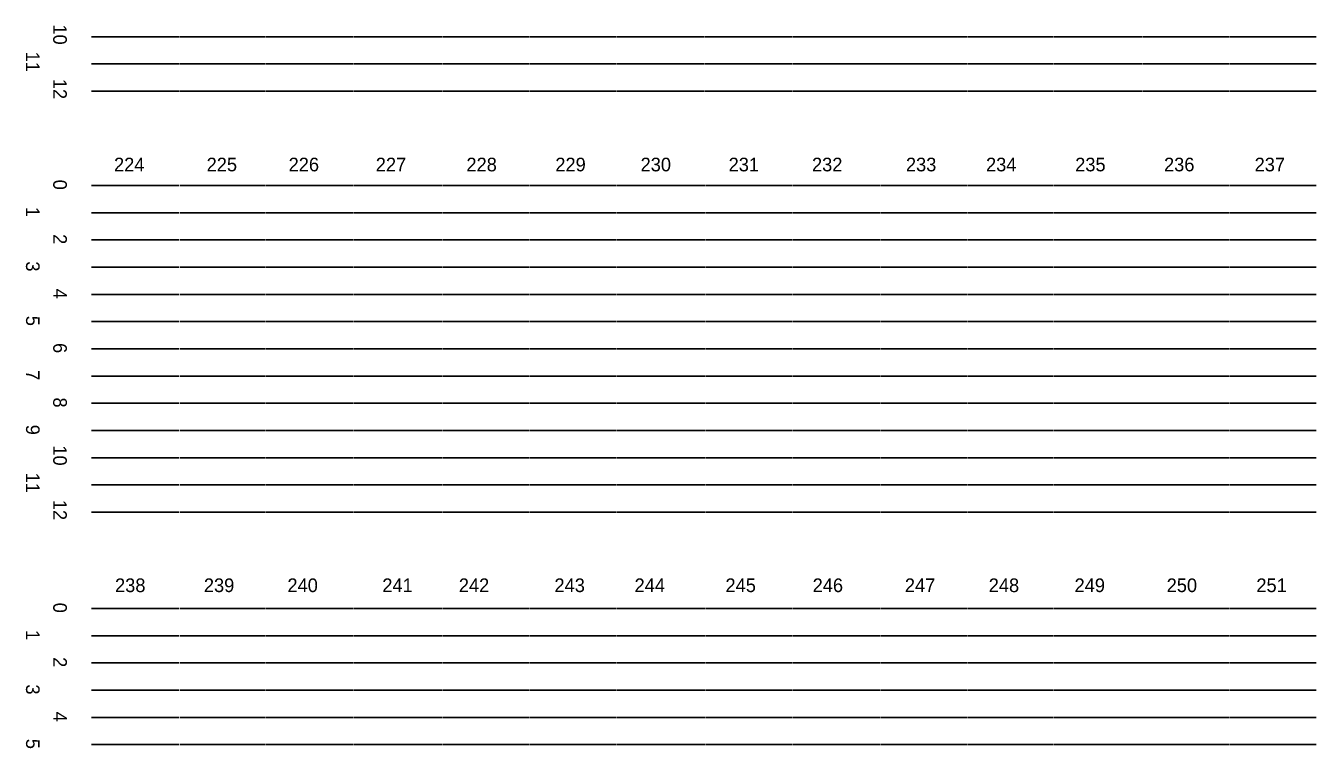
# Model space of a CAD drawing. Extents: x 11193 to 12507, y 10092 to 10555.
# Drawn here: x 11683 to 11888.4, y 10324.2 to 10439.2 of the extents above; entities that cross this region are included whole.
import ezdxf

# ---------------------------------------------------------------- set-up
doc = ezdxf.new("R2010")
doc.units = 0
doc.layers.add('Level 2', color=7, linetype='Continuous')

msp = doc.modelspace()

# ---------------------------------------------------------------- linework, layer by layer
at = {"layer": 'Level 2'}
for p, q in [((11693.42, 10437.46), (11707.34, 10437.46)), ((11707.44, 10437.46), (11721.02, 10437.46)), ((11721.12, 10437.46), (11735.1, 10437.46)), ((11735.2, 10437.46), (11749.18, 10437.46)), ((11749.29, 10437.46), (11763.06, 10437.46)), ((11763.17, 10437.46), (11776.94, 10437.46)), ((11777.05, 10437.46), (11791.02, 10437.46)), ((11791.13, 10437.46), (11804.91, 10437.46)), ((11805.02, 10437.46), (11818.99, 10437.46)), ((11819.09, 10437.46), (11832.87, 10437.46)), ((11832.98, 10437.46), (11846.54, 10437.46)), ((11846.65, 10437.46), (11860.62, 10437.46)), ((11860.73, 10437.46), (11874.51, 10437.46)), ((11874.62, 10437.46), (11888.36, 10437.46)), ((11693.42, 10433.13), (11707.34, 10433.13)), ((11707.44, 10433.13), (11721.02, 10433.13)), ((11721.12, 10433.13), (11735.1, 10433.13)), ((11735.2, 10433.13), (11749.18, 10433.13)), ((11749.29, 10433.13), (11763.06, 10433.13)), ((11763.17, 10433.13), (11776.94, 10433.13)), ((11777.05, 10433.13), (11791.02, 10433.13)), ((11791.13, 10433.13), (11804.91, 10433.13)), ((11805.02, 10433.13), (11818.99, 10433.13)), ((11819.09, 10433.13), (11832.87, 10433.13)), ((11832.98, 10433.13), (11846.54, 10433.13)), ((11846.65, 10433.13), (11860.62, 10433.13)), ((11860.73, 10433.13), (11874.51, 10433.13)), ((11874.62, 10433.13), (11888.36, 10433.13)), ((11693.42, 10428.8), (11707.34, 10428.8)), ((11707.44, 10428.8), (11721.02, 10428.8)), ((11721.12, 10428.8), (11735.1, 10428.8)), ((11735.2, 10428.8), (11749.18, 10428.8)), ((11749.29, 10428.8), (11763.06, 10428.8)), ((11763.17, 10428.8), (11776.94, 10428.8)), ((11777.05, 10428.8), (11791.02, 10428.8)), ((11791.13, 10428.8), (11804.91, 10428.8)), ((11805.02, 10428.8), (11818.99, 10428.8)), ((11819.09, 10428.8), (11832.87, 10428.8)), ((11832.98, 10428.8), (11846.54, 10428.8)), ((11846.65, 10428.8), (11860.62, 10428.8)), ((11860.73, 10428.8), (11874.51, 10428.8)), ((11874.62, 10428.8), (11888.36, 10428.8)), ((11693.42, 10413.78), (11707.35, 10413.78)), ((11707.47, 10413.78), (11721.03, 10413.78)), ((11721.14, 10413.78), (11735.11, 10413.78)), ((11735.23, 10413.78), (11749.19, 10413.78)), ((11749.31, 10413.78), (11763.08, 10413.78)), ((11763.19, 10413.78), (11776.96, 10413.78)), ((11777.06, 10413.78), (11791.04, 10413.78)), ((11791.14, 10413.78), (11804.92, 10413.78)), ((11805.02, 10413.78), (11819.01, 10413.78)), ((11819.11, 10413.78), (11832.88, 10413.78)), ((11832.98, 10413.78), (11846.56, 10413.78)), ((11846.66, 10413.78), (11860.64, 10413.78)), ((11860.74, 10413.78), (11874.52, 10413.78)), ((11874.63, 10413.78), (11888.36, 10413.78)), ((11693.42, 10409.45), (11707.35, 10409.45)), ((11707.47, 10409.45), (11721.03, 10409.45)), ((11721.14, 10409.45), (11735.11, 10409.45)), ((11735.23, 10409.45), (11749.19, 10409.45)), ((11749.31, 10409.45), (11763.08, 10409.45)), ((11763.19, 10409.45), (11776.96, 10409.45)), ((11777.06, 10409.45), (11791.04, 10409.45)), ((11791.14, 10409.45), (11804.92, 10409.45)), ((11805.02, 10409.45), (11819.01, 10409.45)), ((11819.11, 10409.45), (11832.88, 10409.45)), ((11832.98, 10409.45), (11846.56, 10409.45)), ((11846.66, 10409.45), (11860.64, 10409.45)), ((11860.74, 10409.45), (11874.52, 10409.45)), ((11874.63, 10409.45), (11888.36, 10409.45)), ((11693.42, 10405.11), (11707.35, 10405.11)), ((11707.47, 10405.11), (11721.03, 10405.11)), ((11721.14, 10405.11), (11735.11, 10405.11)), ((11735.23, 10405.11), (11749.19, 10405.11)), ((11749.31, 10405.11), (11763.08, 10405.11)), ((11763.19, 10405.11), (11776.96, 10405.11)), ((11777.06, 10405.11), (11791.04, 10405.11)), ((11791.14, 10405.11), (11804.92, 10405.11)), ((11805.02, 10405.11), (11819.01, 10405.11)), ((11819.11, 10405.11), (11832.88, 10405.11)), ((11832.98, 10405.11), (11846.56, 10405.11)), ((11846.66, 10405.11), (11860.64, 10405.11)), ((11860.74, 10405.11), (11874.52, 10405.11)), ((11874.63, 10405.11), (11888.36, 10405.11)), ((11693.42, 10400.78), (11707.35, 10400.78)), ((11707.47, 10400.78), (11721.03, 10400.78)), ((11721.14, 10400.78), (11735.11, 10400.78)), ((11735.23, 10400.78), (11749.19, 10400.78)), ((11749.31, 10400.78), (11763.08, 10400.78)), ((11763.19, 10400.78), (11776.96, 10400.78)), ((11777.06, 10400.78), (11791.04, 10400.78)), ((11791.14, 10400.78), (11804.92, 10400.78)), ((11805.02, 10400.78), (11819.01, 10400.78)), ((11819.11, 10400.78), (11832.88, 10400.78)), ((11832.98, 10400.78), (11846.56, 10400.78)), ((11846.66, 10400.78), (11860.64, 10400.78)), ((11860.74, 10400.78), (11874.52, 10400.78)), ((11874.63, 10400.78), (11888.36, 10400.78)), ((11693.42, 10396.45), (11707.35, 10396.45)), ((11707.47, 10396.45), (11721.03, 10396.45)), ((11721.14, 10396.45), (11735.11, 10396.45)), ((11735.23, 10396.45), (11749.19, 10396.45)), ((11749.31, 10396.45), (11763.08, 10396.45)), ((11763.19, 10396.45), (11776.96, 10396.45)), ((11777.06, 10396.45), (11791.04, 10396.45)), ((11791.14, 10396.45), (11804.92, 10396.45)), ((11805.02, 10396.45), (11819.01, 10396.45)), ((11819.11, 10396.45), (11832.88, 10396.45)), ((11832.98, 10396.45), (11846.56, 10396.45)), ((11846.66, 10396.45), (11860.64, 10396.45)), ((11860.74, 10396.45), (11874.52, 10396.45)), ((11874.63, 10396.45), (11888.36, 10396.45)), ((11693.42, 10392.12), (11707.35, 10392.12)), ((11707.47, 10392.12), (11721.03, 10392.12)), ((11721.14, 10392.12), (11735.11, 10392.12)), ((11735.23, 10392.12), (11749.19, 10392.12)), ((11749.31, 10392.12), (11763.08, 10392.12)), ((11763.19, 10392.12), (11776.96, 10392.12)), ((11777.06, 10392.12), (11791.04, 10392.12)), ((11791.14, 10392.12), (11804.92, 10392.12)), ((11805.02, 10392.12), (11819.01, 10392.12)), ((11819.11, 10392.12), (11832.88, 10392.12)), ((11832.98, 10392.12), (11846.56, 10392.12)), ((11846.66, 10392.12), (11860.64, 10392.12)), ((11860.74, 10392.12), (11874.52, 10392.12)), ((11874.63, 10392.12), (11888.36, 10392.12)), ((11693.42, 10387.79), (11707.35, 10387.79)), ((11707.47, 10387.79), (11721.03, 10387.79)), ((11721.14, 10387.79), (11735.11, 10387.79)), ((11735.23, 10387.79), (11749.19, 10387.79)), ((11749.31, 10387.79), (11763.08, 10387.79)), ((11763.19, 10387.79), (11776.96, 10387.79)), ((11777.06, 10387.79), (11791.04, 10387.79)), ((11791.14, 10387.79), (11804.92, 10387.79)), ((11805.02, 10387.79), (11819.01, 10387.79)), ((11819.11, 10387.79), (11832.88, 10387.79)), ((11832.98, 10387.79), (11846.56, 10387.79)), ((11846.66, 10387.79), (11860.64, 10387.79)), ((11860.74, 10387.79), (11874.52, 10387.79)), ((11874.63, 10387.79), (11888.36, 10387.79)), ((11693.42, 10383.45), (11707.35, 10383.45)), ((11707.47, 10383.45), (11721.03, 10383.45)), ((11721.14, 10383.45), (11735.11, 10383.45)), ((11735.23, 10383.45), (11749.19, 10383.45)), ((11749.31, 10383.45), (11763.08, 10383.45)), ((11763.19, 10383.45), (11776.96, 10383.45)), ((11777.06, 10383.45), (11791.04, 10383.45)), ((11791.14, 10383.45), (11804.92, 10383.45)), ((11805.02, 10383.45), (11819.01, 10383.45)), ((11819.11, 10383.45), (11832.88, 10383.45)), ((11832.98, 10383.45), (11846.56, 10383.45)), ((11846.66, 10383.45), (11860.64, 10383.45)), ((11860.74, 10383.45), (11874.52, 10383.45)), ((11874.63, 10383.45), (11888.36, 10383.45)), ((11693.42, 10379.12), (11707.35, 10379.12)), ((11707.47, 10379.12), (11721.03, 10379.12)), ((11721.14, 10379.12), (11735.11, 10379.12)), ((11735.23, 10379.12), (11749.19, 10379.12)), ((11749.31, 10379.12), (11763.08, 10379.12)), ((11763.19, 10379.12), (11776.96, 10379.12)), ((11777.06, 10379.12), (11791.04, 10379.12)), ((11791.14, 10379.12), (11804.92, 10379.12)), ((11805.02, 10379.12), (11819.01, 10379.12)), ((11819.11, 10379.12), (11832.88, 10379.12)), ((11832.98, 10379.12), (11846.56, 10379.12)), ((11846.66, 10379.12), (11860.64, 10379.12)), ((11860.74, 10379.12), (11874.52, 10379.12)), ((11874.63, 10379.12), (11888.36, 10379.12)), ((11693.42, 10374.79), (11707.35, 10374.79)), ((11707.47, 10374.79), (11721.03, 10374.79)), ((11721.14, 10374.79), (11735.11, 10374.79)), ((11735.23, 10374.79), (11749.19, 10374.79)), ((11749.31, 10374.79), (11763.08, 10374.79)), ((11763.19, 10374.79), (11776.96, 10374.79)), ((11777.06, 10374.79), (11791.04, 10374.79)), ((11791.14, 10374.79), (11804.92, 10374.79)), ((11805.02, 10374.79), (11819.01, 10374.79)), ((11819.11, 10374.79), (11832.88, 10374.79)), ((11832.98, 10374.79), (11846.56, 10374.79)), ((11846.66, 10374.79), (11860.64, 10374.79)), ((11860.74, 10374.79), (11874.52, 10374.79)), ((11874.63, 10374.79), (11888.36, 10374.79)), ((11693.42, 10370.46), (11707.35, 10370.46)), ((11707.47, 10370.46), (11721.03, 10370.46)), ((11721.14, 10370.46), (11735.11, 10370.46)), ((11735.23, 10370.46), (11749.19, 10370.46)), ((11749.31, 10370.46), (11763.08, 10370.46)), ((11763.19, 10370.46), (11776.96, 10370.46)), ((11777.06, 10370.46), (11791.04, 10370.46)), ((11791.14, 10370.46), (11804.92, 10370.46)), ((11805.02, 10370.46), (11819.01, 10370.46)), ((11819.11, 10370.46), (11832.88, 10370.46)), ((11832.98, 10370.46), (11846.56, 10370.46)), ((11846.66, 10370.46), (11860.64, 10370.46)), ((11860.74, 10370.46), (11874.52, 10370.46)), ((11874.63, 10370.46), (11888.36, 10370.46)), ((11693.42, 10366.13), (11707.35, 10366.13)), ((11707.47, 10366.13), (11721.03, 10366.13)), ((11721.14, 10366.13), (11735.11, 10366.13)), ((11735.23, 10366.13), (11749.19, 10366.13)), ((11749.31, 10366.13), (11763.08, 10366.13)), ((11763.19, 10366.13), (11776.96, 10366.13)), ((11777.06, 10366.13), (11791.04, 10366.13)), ((11791.14, 10366.13), (11804.92, 10366.13)), ((11805.02, 10366.13), (11819.01, 10366.13)), ((11819.11, 10366.13), (11832.88, 10366.13)), ((11832.98, 10366.13), (11846.56, 10366.13)), ((11846.66, 10366.13), (11860.64, 10366.13)), ((11860.74, 10366.13), (11874.52, 10366.13)), ((11874.63, 10366.13), (11888.36, 10366.13)), ((11693.42, 10361.79), (11707.35, 10361.79)), ((11707.47, 10361.79), (11721.03, 10361.79)), ((11721.14, 10361.79), (11735.11, 10361.79)), ((11735.23, 10361.79), (11749.19, 10361.79)), ((11749.31, 10361.79), (11763.08, 10361.79)), ((11763.19, 10361.79), (11776.96, 10361.79)), ((11777.06, 10361.79), (11791.04, 10361.79)), ((11791.14, 10361.79), (11804.92, 10361.79)), ((11805.02, 10361.79), (11819.01, 10361.79)), ((11819.11, 10361.79), (11832.88, 10361.79)), ((11832.98, 10361.79), (11846.56, 10361.79)), ((11846.66, 10361.79), (11860.64, 10361.79)), ((11860.74, 10361.79), (11874.52, 10361.79)), ((11874.63, 10361.79), (11888.36, 10361.79)), ((11693.42, 10346.46), (11707.35, 10346.46)), ((11707.47, 10346.46), (11721.03, 10346.46)), ((11721.14, 10346.46), (11735.11, 10346.46)), ((11735.23, 10346.46), (11749.19, 10346.46)), ((11749.31, 10346.46), (11763.08, 10346.46)), ((11763.19, 10346.46), (11776.96, 10346.46)), ((11777.06, 10346.46), (11791.04, 10346.46)), ((11791.14, 10346.46), (11804.92, 10346.46)), ((11805.02, 10346.46), (11819.01, 10346.46)), ((11819.11, 10346.46), (11832.88, 10346.46)), ((11832.98, 10346.46), (11846.56, 10346.46)), ((11846.66, 10346.46), (11860.64, 10346.46)), ((11860.74, 10346.46), (11874.52, 10346.46)), ((11874.63, 10346.46), (11888.36, 10346.46)), ((11693.42, 10342.13), (11707.35, 10342.13)), ((11707.47, 10342.13), (11721.03, 10342.13)), ((11721.14, 10342.13), (11735.11, 10342.13)), ((11735.23, 10342.13), (11749.19, 10342.13)), ((11749.31, 10342.13), (11763.08, 10342.13)), ((11763.19, 10342.13), (11776.96, 10342.13)), ((11777.06, 10342.13), (11791.04, 10342.13)), ((11791.14, 10342.13), (11804.92, 10342.13)), ((11805.02, 10342.13), (11819.01, 10342.13)), ((11819.11, 10342.13), (11832.88, 10342.13)), ((11832.98, 10342.13), (11846.56, 10342.13)), ((11846.66, 10342.13), (11860.64, 10342.13)), ((11860.74, 10342.13), (11874.52, 10342.13)), ((11874.63, 10342.13), (11888.36, 10342.13)), ((11693.42, 10337.8), (11707.35, 10337.8)), ((11707.47, 10337.8), (11721.03, 10337.8)), ((11721.14, 10337.8), (11735.11, 10337.8)), ((11735.23, 10337.8), (11749.19, 10337.8)), ((11749.31, 10337.8), (11763.08, 10337.8)), ((11763.19, 10337.8), (11776.96, 10337.8)), ((11777.06, 10337.8), (11791.04, 10337.8)), ((11791.14, 10337.8), (11804.92, 10337.8)), ((11805.02, 10337.8), (11819.01, 10337.8)), ((11819.11, 10337.8), (11832.88, 10337.8)), ((11832.98, 10337.8), (11846.56, 10337.8)), ((11846.66, 10337.8), (11860.64, 10337.8)), ((11860.74, 10337.8), (11874.52, 10337.8)), ((11874.63, 10337.8), (11888.36, 10337.8)), ((11693.42, 10333.46), (11707.35, 10333.46)), ((11707.47, 10333.46), (11721.03, 10333.46)), ((11721.14, 10333.46), (11735.11, 10333.46)), ((11735.23, 10333.46), (11749.19, 10333.46)), ((11749.31, 10333.46), (11763.08, 10333.46)), ((11763.19, 10333.46), (11776.96, 10333.46)), ((11777.06, 10333.46), (11791.04, 10333.46)), ((11791.14, 10333.46), (11804.92, 10333.46)), ((11805.02, 10333.46), (11819.01, 10333.46)), ((11819.11, 10333.46), (11832.88, 10333.46)), ((11832.98, 10333.46), (11846.56, 10333.46)), ((11846.66, 10333.46), (11860.64, 10333.46)), ((11860.74, 10333.46), (11874.52, 10333.46)), ((11874.63, 10333.46), (11888.36, 10333.46)), ((11693.42, 10329.13), (11707.35, 10329.13)), ((11707.47, 10329.13), (11721.03, 10329.13)), ((11721.14, 10329.13), (11735.11, 10329.13)), ((11735.23, 10329.13), (11749.19, 10329.13)), ((11749.31, 10329.13), (11763.08, 10329.13)), ((11763.19, 10329.13), (11776.96, 10329.13)), ((11777.06, 10329.13), (11791.04, 10329.13)), ((11791.14, 10329.13), (11804.92, 10329.13)), ((11805.02, 10329.13), (11819.01, 10329.13)), ((11819.11, 10329.13), (11832.88, 10329.13)), ((11832.98, 10329.13), (11846.56, 10329.13)), ((11846.66, 10329.13), (11860.64, 10329.13)), ((11860.74, 10329.13), (11874.52, 10329.13)), ((11874.63, 10329.13), (11888.36, 10329.13)), ((11693.42, 10324.8), (11707.35, 10324.8)), ((11707.47, 10324.8), (11721.03, 10324.8)), ((11721.14, 10324.8), (11735.11, 10324.8)), ((11735.23, 10324.8), (11749.19, 10324.8)), ((11749.31, 10324.8), (11763.08, 10324.8)), ((11763.19, 10324.8), (11776.96, 10324.8)), ((11777.06, 10324.8), (11791.04, 10324.8)), ((11791.14, 10324.8), (11804.92, 10324.8)), ((11805.02, 10324.8), (11819.01, 10324.8)), ((11819.11, 10324.8), (11832.88, 10324.8)), ((11832.98, 10324.8), (11846.56, 10324.8)), ((11846.66, 10324.8), (11860.64, 10324.8)), ((11860.74, 10324.8), (11874.52, 10324.8)), ((11874.63, 10324.8), (11888.36, 10324.8))]:
    msp.add_line(p, q, dxfattribs=at)

# ---------------------------------------------------------------- texts
for s, height, p in [('10', 2.166, (11687.34, 10439.41)), ('11', 2.166, (11683.01, 10435.08)), ('12', 2.166, (11687.34, 10430.75)), ('0', 2.17, (11687.34, 10414.7)), ('1', 2.17, (11683.01, 10410.37)), ('2', 2.17, (11687.34, 10406.04)), ('3', 2.17, (11683.01, 10401.7)), ('4', 2.17, (11687.34, 10397.37)), ('5', 2.17, (11683.01, 10393.04)), ('6', 2.17, (11687.34, 10388.71)), ('7', 2.17, (11683.01, 10384.38)), ('8', 2.17, (11687.34, 10380.04)), ('9', 2.17, (11683.01, 10375.71)), ('10', 2.166, (11687.34, 10372.42)), ('11', 2.166, (11683.01, 10368.08)), ('12', 2.166, (11687.34, 10363.75)), ('0', 2.17, (11687.34, 10347.38)), ('1', 2.17, (11683.01, 10343.05)), ('2', 2.17, (11687.34, 10338.72)), ('3', 2.17, (11683.01, 10334.38)), ('4', 2.17, (11687.34, 10330.05)), ('5', 2.17, (11683.01, 10325.72))]:
    msp.add_text(s, height=height, rotation=270, dxfattribs=at).set_placement(p)
for s, p in [('224', (11697.02, 10416.03)), ('225', (11711.76, 10416.03)), ('226', (11724.81, 10416.03)), ('227', (11738.68, 10416.03)), ('228', (11753.11, 10416.03)), ('229', (11767.26, 10416.03)), ('230', (11780.83, 10416.03)), ('231', (11794.84, 10416.03)), ('232', (11808.11, 10416.03)), ('233', (11823.06, 10416.03)), ('234', (11835.81, 10416.03)), ('235', (11850, 10416.03)), ('236', (11864.14, 10416.03)), ('237', (11878.56, 10416.03)), ('238', (11697.18, 10349.07)), ('239', (11711.32, 10349.07)), ('240', (11724.62, 10349.07)), ('241', (11739.72, 10349.07)), ('242', (11751.9, 10349.07)), ('243', (11767.12, 10349.07)), ('244', (11779.87, 10349.07)), ('245', (11794.34, 10349.07)), ('246', (11808.21, 10349.07)), ('247', (11822.89, 10349.07)), ('248', (11836.24, 10349.07)), ('249', (11849.9, 10349.07)), ('250', (11864.56, 10349.07)), ('251', (11878.84, 10349.07))]:
    msp.add_text(s, height=2.17, dxfattribs=at).set_placement(p)

doc.saveas('drawing.dxf')
